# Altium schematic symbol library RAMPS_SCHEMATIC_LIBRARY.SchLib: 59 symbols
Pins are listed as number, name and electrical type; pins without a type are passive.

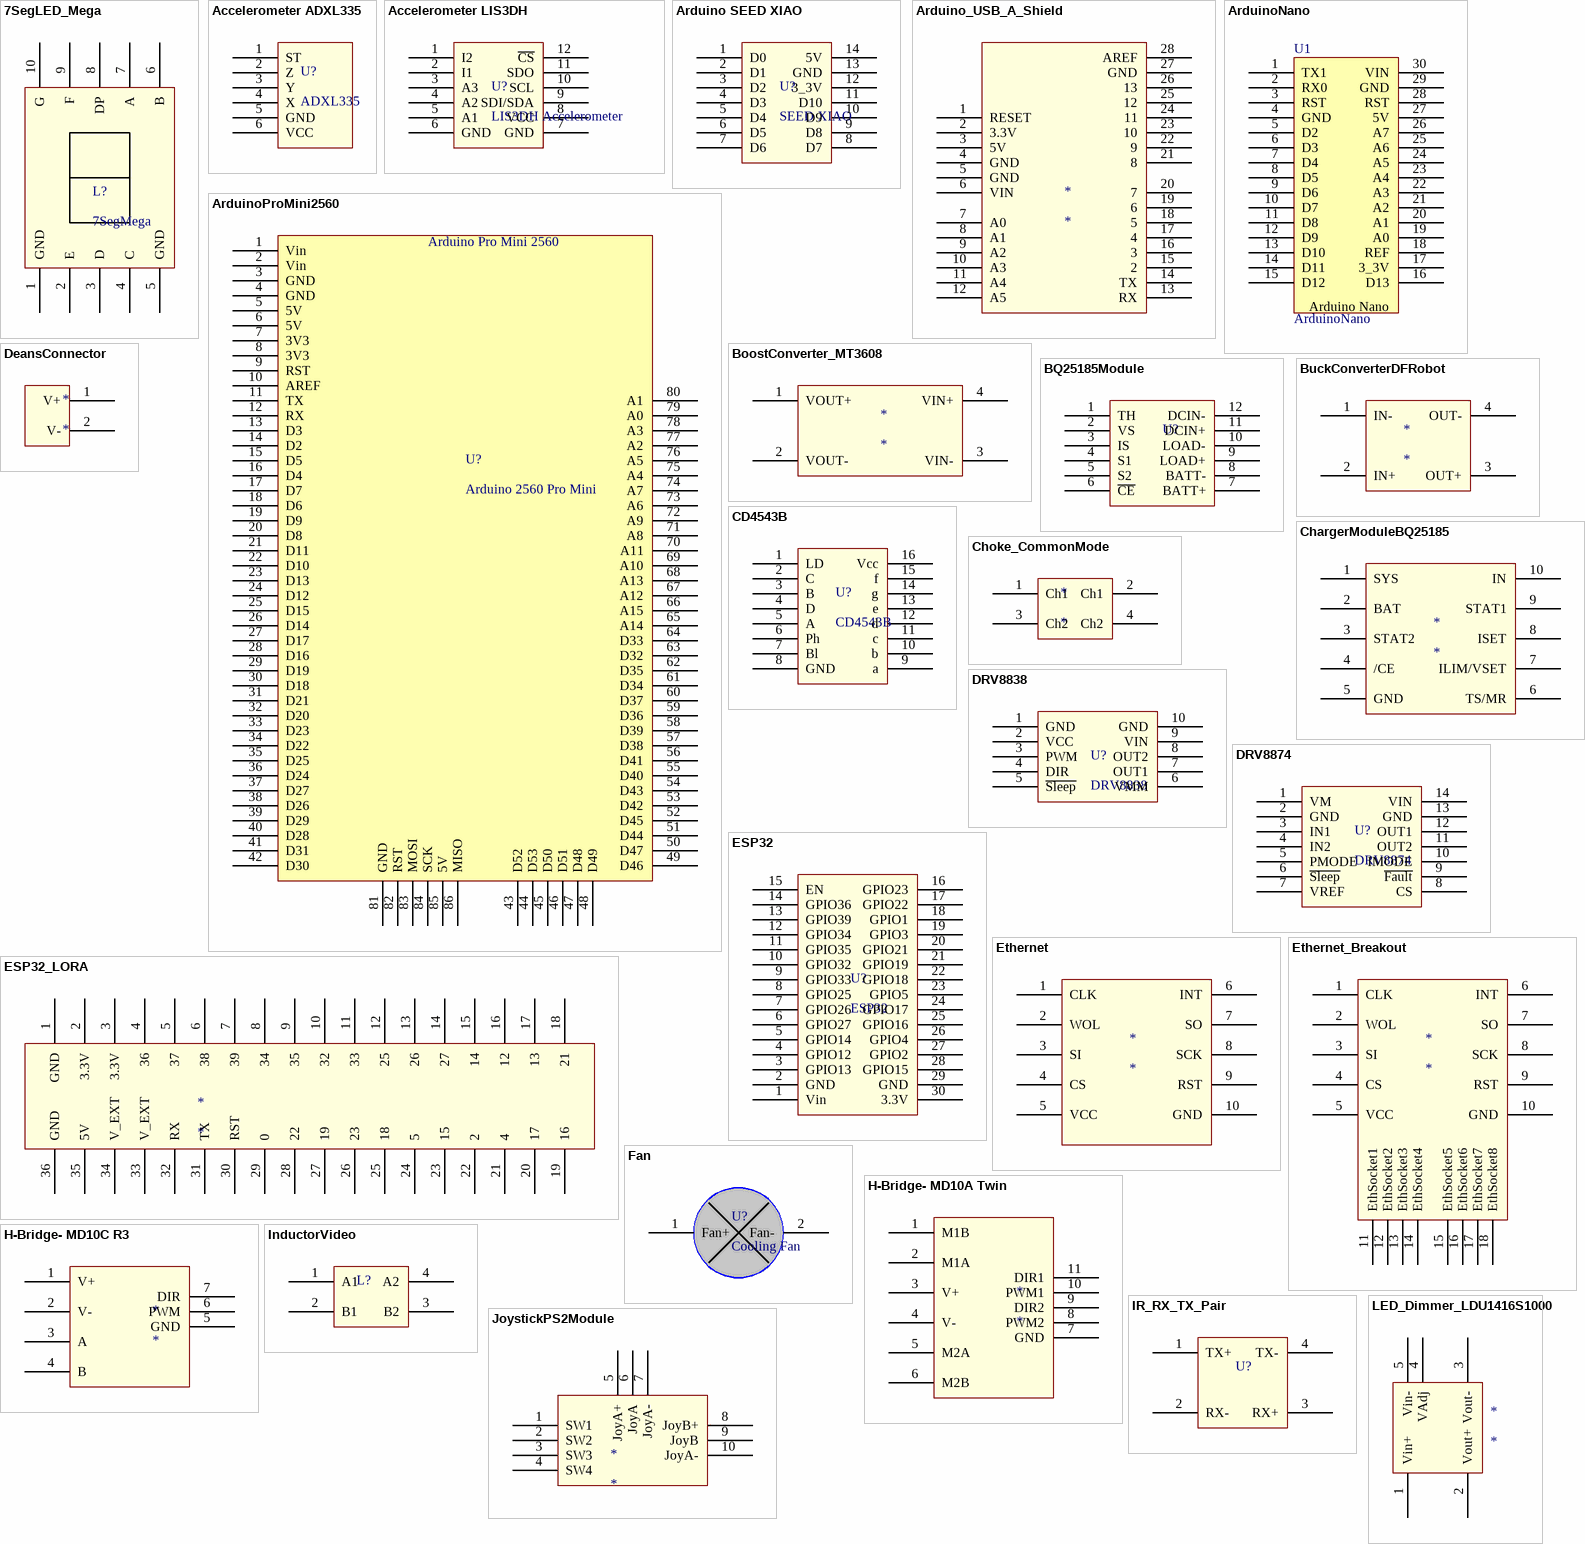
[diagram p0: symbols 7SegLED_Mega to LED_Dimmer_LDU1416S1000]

## 7SegLED_Mega
designator L?, comment 7SegMega
pins: 1 GND, 2 E, 3 D, 4 C, 5 GND, 6 B, 7 A, 8 DP, 9 F, 10 G

## Accelerometer ADXL335
designator U?, comment ADXL335
pins: 1 ST, 2 Z, 3 Y, 4 X, 5 GND, 6 VCC

## Accelerometer LIS3DH
designator U?, comment LIS3DH Accelerometer
pins: 1 I2, 2 I1, 3 A3, 4 A2, 5 A1, 6 GND, 7 GND, 8 VCC, 9 SDI/SDA, 10 SCL, 11 SDO, 12 ~{CS}

## Arduino SEED XIAO
designator U?, comment SEED XIAO
pins: 1 D0, 2 D1, 3 D2, 4 D3, 5 D4, 6 D5, 7 D6, 8 D7, 9 D8, 10 D9, 11 D10, 12 3_3V, 13 GND, 14 5V

## Arduino_USB_A_Shield
designator *
pins: 1 RESET, 2 3.3V, 3 5V, 4 GND, 5 GND, 6 VIN, 7 A0, 8 A1, 9 A2, 10 A3, 11 A4, 12 A5, 13 RX, 14 TX, 15 2, 16 3, 17 4, 18 5, 19 6, 20 7, 21 8, 22 9, 23 10, 24 11, 25 12, 26 13, 27 GND, 28 AREF

## ArduinoNano
designator U1
footprint ArduinoNano
footprint ArduinoNano
pins: 1 TX1, 2 RX0, 3 RST, 4 GND, 5 D2, 6 D3, 7 D4, 8 D5, 9 D6, 10 D7, 11 D8, 12 D9, 13 D10, 14 D11, 15 D12, 16 D13, 17 3_3V, 18 REF, 19 A0, 20 A1, 21 A2, 22 A3, 23 A4, 24 A5, 25 A6, 26 A7, 27 5V, 28 RST, 29 GND, 30 VIN

## ArduinoProMini2560
designator U?, comment Arduino 2560 Pro Mini
pins: 1 Vin, 2 Vin, 3 GND, 4 GND, 5 5V, 6 5V, 7 3V3, 8 3V3, 9 RST, 10 AREF, 11 TX, 12 RX, 13 D3, 14 D2, 15 D5, 16 D4, 17 D7, 18 D6, 19 D9, 20 D8, 21 D11, 22 D10, 23 D13, 24 D12, 25 D15, 26 D14, 27 D17, 28 D16, 29 D19, 30 D18, 31 D21, 32 D20, 33 D23, 34 D22, 35 D25, 36 D24, 37 D27, 38 D26, 39 D29, 40 D28, 41 D31, 42 D30, 43 D52, 44 D53, 45 D50, 46 D51, 47 D48, 48 D49, 49 D46, 50 D47, 51 D44, 52 D45, 53 D42, 54 D43, 55 D40, 56 D41, 57 D38, 58 D39, 59 D36, 60 D37, 61 D34, 62 D35, 63 D32, 64 D33, 65 A14, 66 A15, 67 A12, 68 A13, 69 A10, 70 A11, 71 A8, 72 A9, 73 A6, 74 A7, 75 A4, 76 A5, 77 A2, 78 A3, 79 A0, 80 A1, 81 GND, 82 RST, 83 MOSI, 84 SCK, 85 5V, 86 MISO

## BoostConverter_MT3608
designator *
pins: 1 VOUT+, 2 VOUT-, 3 VIN-, 4 VIN+

## BQ25185Module
designator U?
BQ25185 Charging Module with USB Connector
pins: 1 TH, 2 VS, 3 IS, 4 S1, 5 S2, 6 ~{CE}, 7 BATT+, 8 BATT-, 9 LOAD+, 10 LOAD-, 11 DCIN+, 12 DCIN-

## BuckConverterDFRobot
designator *
pins: 1 IN-, 2 IN+, 3 OUT+, 4 OUT-

## CD4543B
designator U?
pins: 1 LD, 2 C, 3 B, 4 D, 5 A, 6 Ph, 7 Bl, 8 GND, 9 a, 10 b, 11 c, 12 d, 13 e, 14 g, 15 f, 16 Vcc

## ChargerModuleBQ25185
designator *
pins: 1 SYS, 2 BAT, 3 STAT2, 4 /CE, 5 GND, 6 TS/MR, 7 ILIM/VSET, 8 ISET, 9 STAT1, 10 IN

## Choke_CommonMode
designator *
pins: 1 Ch1, 2 Ch1, 3 Ch2, 4 Ch2

## DeansConnector
designator *
pins: 1 V+, 2 V-

## DRV8838
designator U?
Motor Driver 1.7A
pins: 1 GND, 2 VCC, 3 PWM, 4 DIR, 5 ~{Sleep}, 6 VMM, 7 OUT1, 8 OUT2, 9 VIN, 10 GND

## DRV8874
designator U?
Motor Driver 2.1A
pins: 1 VM, 2 GND, 3 IN1, 4 IN2, 5 PMODE, 6 ~{Sleep}, 7 VREF, 8 CS, 9 ~{Fault}, 10 IMODE, 11 OUT2, 12 OUT1, 13 GND, 14 VIN

## ESP32
designator U?
pins: 1 Vin, 2 GND, 3 GPIO13, 4 GPIO12, 5 GPIO14, 6 GPIO27, 7 GPIO26, 8 GPIO25, 9 GPIO33, 10 GPIO32, 11 GPIO35, 12 GPIO34, 13 GPIO39, 14 GPIO36, 15 EN, 16 GPIO23, 17 GPIO22, 18 GPIO1, 19 GPIO3, 20 GPIO21, 21 GPIO19, 22 GPIO18, 23 GPIO5, 24 GPIO17, 25 GPIO16, 26 GPIO4, 27 GPIO2, 28 GPIO15, 29 GND, 30 3.3V

## ESP32_LORA
designator *
pins: 1 GND, 2 3.3V, 3 3.3V, 4 36, 5 37, 6 38, 7 39, 8 34, 9 35, 10 32, 11 33, 12 25, 13 26, 14 27, 15 14, 16 12, 17 13, 18 21, 19 16, 20 17, 21 4, 22 2, 23 15, 24 5, 25 18, 26 23, 27 19, 28 22, 29 0, 30 RST, 31 TX, 32 RX, 33 V_EXT, 34 V_EXT, 35 5V, 36 GND

## Ethernet
designator *
pins: 1 CLK, 2 WOL, 3 SI, 4 CS, 5 VCC, 6 INT, 7 SO, 8 SCK, 9 RST, 10 GND

## Ethernet_Breakout
designator *
Includes breakout of each of the pins for the ethernet socket
pins: 1 CLK, 2 WOL, 3 SI, 4 CS, 5 VCC, 6 INT, 7 SO, 8 SCK, 9 RST, 10 GND, 11 EthSocket1, 12 EthSocket2, 13 EthSocket3, 14 EthSocket4, 15 EthSocket5, 16 EthSocket6, 17 EthSocket7, 18 EthSocket8

## Fan
designator U?, comment Cooling Fan
pins: 1 Fan+, 2 Fan-

## H-Bridge- MD10A Twin
designator *
pins: 1 M1B, 2 M1A, 3 V+, 4 V-, 5 M2A, 6 M2B, 7 GND, 8 PWM2, 9 DIR2, 10 PWM1, 11 DIR1

## H-Bridge- MD10C R3
designator *
pins: 1 V+, 2 V-, 3 A, 4 B, 5 GND, 6 PWM, 7 DIR

## InductorVideo
designator L?
VideoInductor
pins: 1 A1, 2 B1, 3 B2, 4 A2

## IR_RX_TX_Pair
designator U?
pins: 1 TX+, 2 RX-, 3 RX+, 4 TX-

## JoystickPS2Module
designator *
pins: 1 SW1, 2 SW2, 3 SW3, 4 SW4, 5 JoyA+, 6 JoyA, 7 JoyA-, 8 JoyB+, 9 JoyB, 10 JoyA-

## LED_Dimmer_LDU1416S1000
designator *
pins: 1 Vin+, 2 Vout+, 3 Vout-, 4 VAdj, 5 Vin-

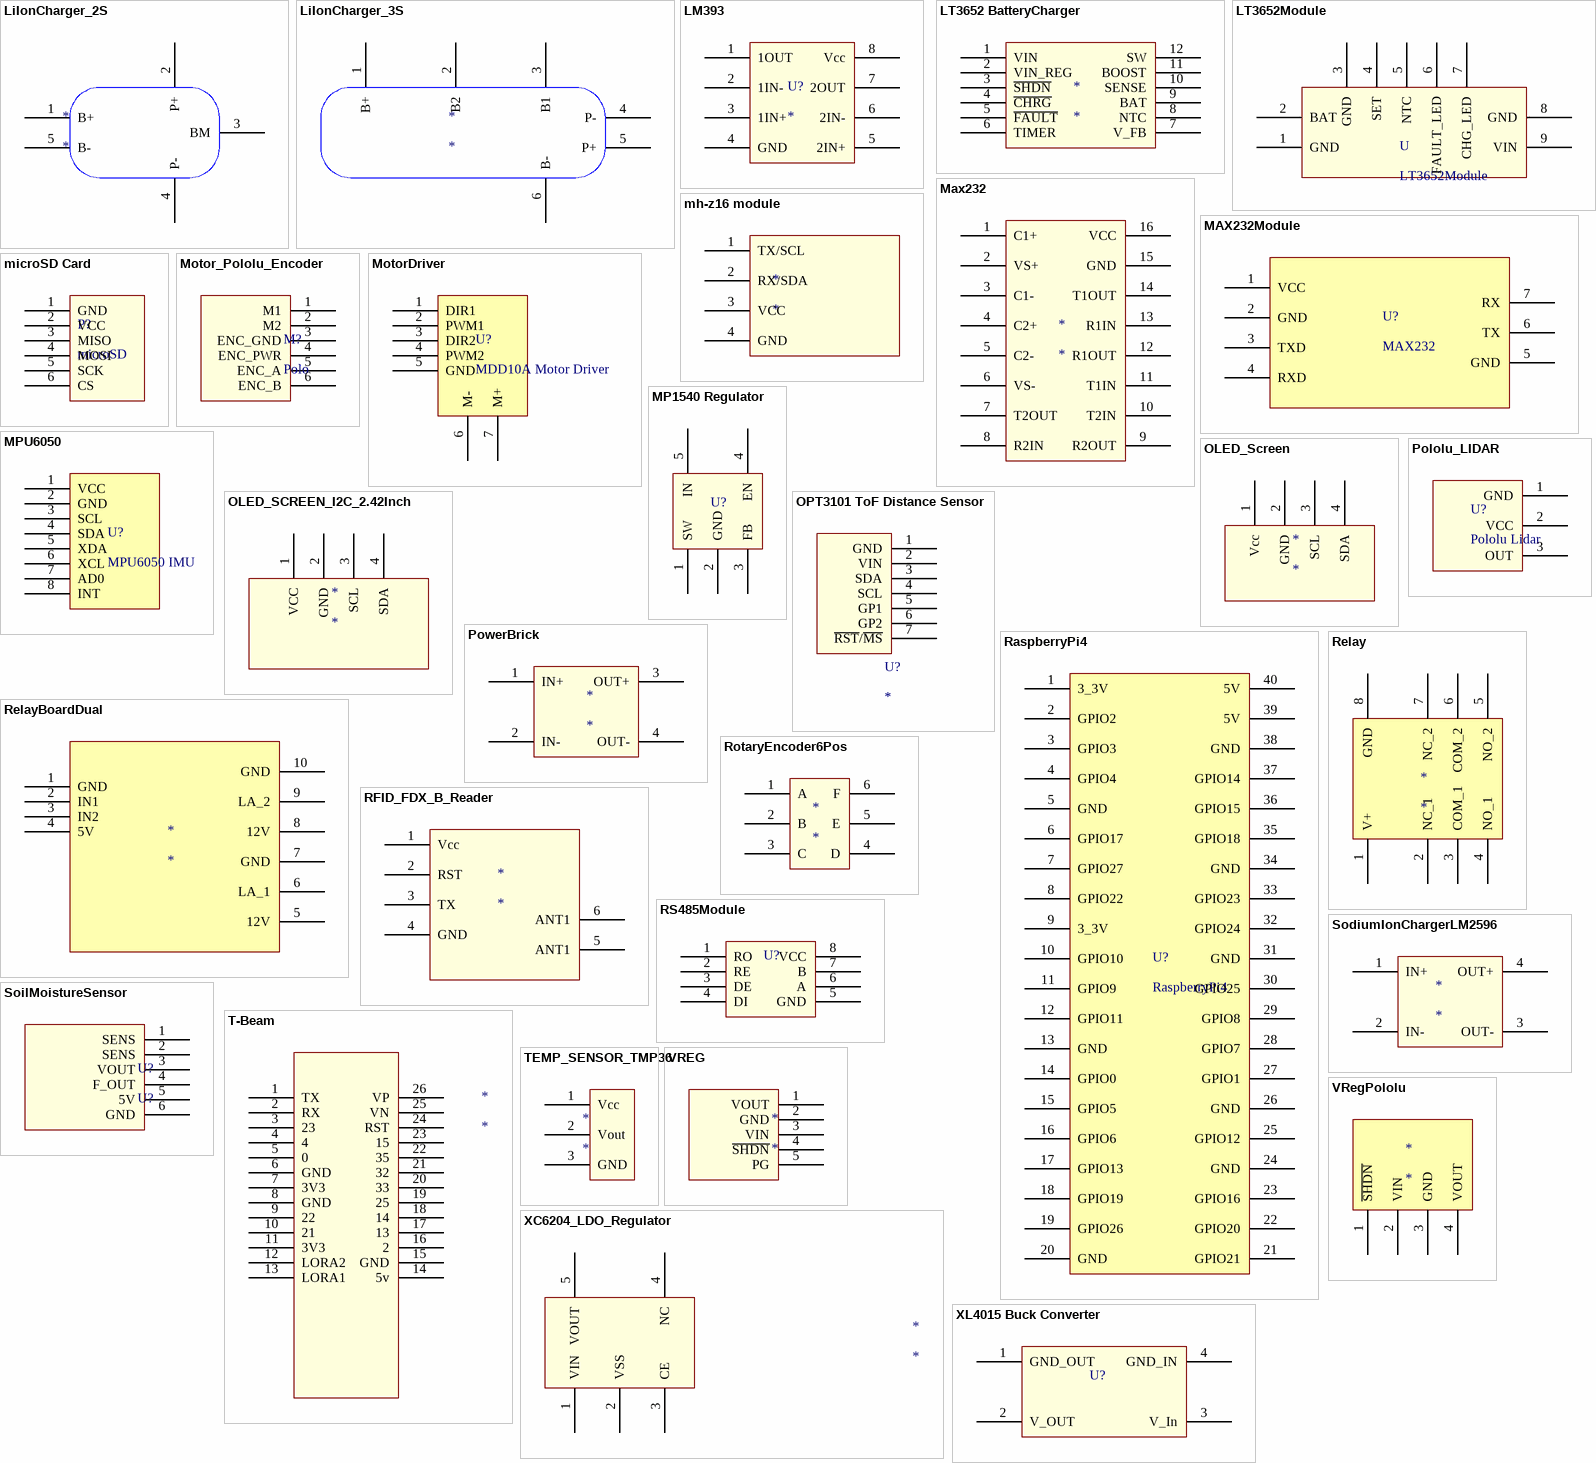
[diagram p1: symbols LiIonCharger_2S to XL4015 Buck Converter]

## LiIonCharger_2S
designator *
pins: 1 B+, 2 P+, 3 BM, 4 P-, 5 B-

## LiIonCharger_3S
designator *
pins: 1 B+, 2 B2, 3 B1, 4 P-, 5 P+, 6 B-

## LM393
designator U?
pins: 1 1OUT, 2 1IN-, 3 1IN+, 4 GND, 5 2IN+, 6 2IN-, 7 2OUT, 8 Vcc

## LT3652 BatteryCharger
designator *
pins: 1 VIN, 2 VIN_REG, 3 ~{SHDN}, 4 ~{CHRG}, 5 ~{FAULT}, 6 TIMER, 7 V_FB, 8 NTC, 9 BAT, 10 SENSE, 11 BOOST, 12 SW

## LT3652Module
designator U
pins: 1 GND, 2 BAT, 3 GND, 4 SET, 5 NTC, 6 FAULT_LED, 7 CHG_LED, 8 GND, 9 VIN

## Max232
designator *
pins: 1 C1+, 2 VS+, 3 C1-, 4 C2+, 5 C2-, 6 VS-, 7 T2OUT, 8 R2IN, 9 R2OUT, 10 T2IN, 11 T1IN, 12 R1OUT, 13 R1IN, 14 T1OUT, 15 GND, 16 VCC

## MAX232Module
designator U?, comment MAX232
pins: 1 VCC, 2 GND, 3 TXD, 4 RXD, 5 GND, 6 TX, 7 RX

## mh-z16 module
designator *
pins: 1 TX/SCL, 2 RX/SDA, 3 VCC, 4 GND

## microSD Card
designator P?, comment microSD
pins: 1 GND, 2 VCC, 3 MISO, 4 MOSI, 5 SCK, 6 CS

## Motor_Pololu_Encoder
designator M?, comment Polo
100:1 Metal Gearmotor 37Dx73L mm 12V with 64 CPR Encoder Pololu-4755
pins: 1 M1, 2 M2, 3 ENC_GND, 4 ENC_PWR, 5 ENC_A, 6 ENC_B

## MotorDriver
designator U?, comment MDD10A Motor Driver
pins: 1 DIR1, 2 PWM1, 3 DIR2, 4 PWM2, 5 GND, 6 M-, 7 M+

## MP1540 Regulator
designator U?
DC-DC Regulator for use with RFID Readers
pins: 1 SW, 2 GND, 3 FB, 4 EN, 5 IN

## MPU6050
designator U?, comment MPU6050 IMU
pins: 1 VCC, 2 GND, 3 SCL, 4 SDA, 5 XDA, 6 XCL, 7 AD0, 8 INT

## OLED_Screen
designator *
pins: 1 Vcc, 2 GND, 3 SCL, 4 SDA

## OLED_SCREEN_I2C_2.42Inch
designator *
pins: 1 VCC, 2 GND, 3 SCL, 4 SDA

## OPT3101 ToF Distance Sensor
designator U?
3-Channel Wide FOV Time-of-Flight Distance Sensor for TI-RSLK MAX Using OPT3101 TI
pins: 1 GND, 2 VIN, 3 SDA, 4 SCL, 5 GP1, 6 GP2, 7 ~{RST}/~{MS}

## Pololu_LIDAR
designator U?, comment Pololu Lidar
pins: 1 GND, 2 VCC, 3 OUT

## PowerBrick
designator *
pins: 1 IN+, 2 IN-, 3 OUT+, 4 OUT-

## RaspberryPi4
designator U?
pins: 1 3_3V, 2 GPIO2, 3 GPIO3, 4 GPIO4, 5 GND, 6 GPIO17, 7 GPIO27, 8 GPIO22, 9 3_3V, 10 GPIO10, 11 GPIO9, 12 GPIO11, 13 GND, 14 GPIO0, 15 GPIO5, 16 GPIO6, 17 GPIO13, 18 GPIO19, 19 GPIO26, 20 GND, 21 GPIO21, 22 GPIO20, 23 GPIO16, 24 GND, 25 GPIO12, 26 GND, 27 GPIO1, 28 GPIO7, 29 GPIO8, 30 GPIO25, 31 GND, 32 GPIO24, 33 GPIO23, 34 GND, 35 GPIO18, 36 GPIO15, 37 GPIO14, 38 GND, 39 5V, 40 5V

## Relay
designator *
pins: 1 V+, 2 NC_1, 3 COM_1, 4 NO_1, 5 NO_2, 6 COM_2, 7 NC_2, 8 GND

## RelayBoardDual
designator *
pins: 1 GND, 2 IN1, 3 IN2, 4 5V, 5 12V, 6 LA_1, 7 GND, 8 12V, 9 LA_2, 10 GND

## RFID_FDX_B_Reader
designator *
pins: 1 Vcc, 2 RST, 3 TX, 4 GND, 5 ANT1, 6 ANT1

## RotaryEncoder6Pos
designator *
pins: 1 A, 2 B, 3 C, 4 D, 5 E, 6 F

## RS485Module
designator U?
RS-485 Module
pins: 1 RO, 2 RE, 3 DE, 4 DI, 5 GND, 6 A, 7 B, 8 VCC

## SodiumIonChargerLM2596
designator *
pins: 1 IN+, 2 IN-, 3 OUT-, 4 OUT+

## SoilMoistureSensor
designator U?, comment U?
sms SOIL MOISTURE SENSOR
pins: 1 SENS, 2 SENS, 3 VOUT, 4 F_OUT, 5 5V, 6 GND

## T-Beam
designator *
pins: 1 TX, 2 RX, 3 23, 4, 5 0, 6 GND, 7 3V3, 8 GND, 9 22, 10 21, 11 3V3, 12 LORA2, 13 LORA1, 14 5v, 15 GND, 16 2, 17 13, 18 14, 19 25, 20 33, 21 32, 22 35, 23 15, 24 RST, 25 VN, 26 VP

## TEMP_SENSOR_TMP36
designator *
pins: 1 Vcc, 2 Vout, 3 GND

## VREG
designator *
pins: 1 VOUT, 2 GND, 3 VIN, 4 ~{SHDN}, 5 PG

## VRegPololu
designator *
pins: 1 ~{SHDN}, 2 VIN, 3 GND, 4 VOUT

## XC6204_LDO_Regulator
designator *
pins: 1 VIN, 2 VSS, 3 CE, 4 NC, 5 VOUT

## XL4015 Buck Converter
designator U?
pins: 1 GND_OUT, 2 V_OUT, 3 V_In, 4 GND_IN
